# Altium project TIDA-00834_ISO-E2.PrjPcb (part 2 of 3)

## Sheet TIDA-00834_ISO-E2_Pg7_ COMPARATOR.SchDoc: COMPARATOR FOR ZCD
size 431 x 279 mm; Date: Not shown in title block; ApprovedBy: Not shown in title block; CheckedBy: Not shown in title block; Author: Not shown in title block; CompanyName: Not shown in title block; DrawnBy: Sreenivasa; Engineer: Not shown in title block; Organization: Not shown in title block; Address1: Not shown in title block; Address2: Not shown in title block; Address3: Not shown in title block; Address4: Not shown in title block; DocumentNumber: 1; Revision: Use project parameter SCH_Rev; SheetNumber: 7; SheetTotal: 12; PageSetup: Record=PageOptions¦CenterHorizontal=True¦CenterVertical=True¦PrintScale=1.00¦XCorrection=1.00¦YCorrection=1.00¦PrintKind=0¦BorderSize=5000000¦LeftOffset=0¦BottomOffset=0¦Orientation=2¦PaperLength=1000¦PaperWidth=1000¦Scale=100¦PaperSource=15¦PrintQuality=600¦MediaType=1¦DitherType=10¦PaperKind=Letter¦PrintScaleMode=1
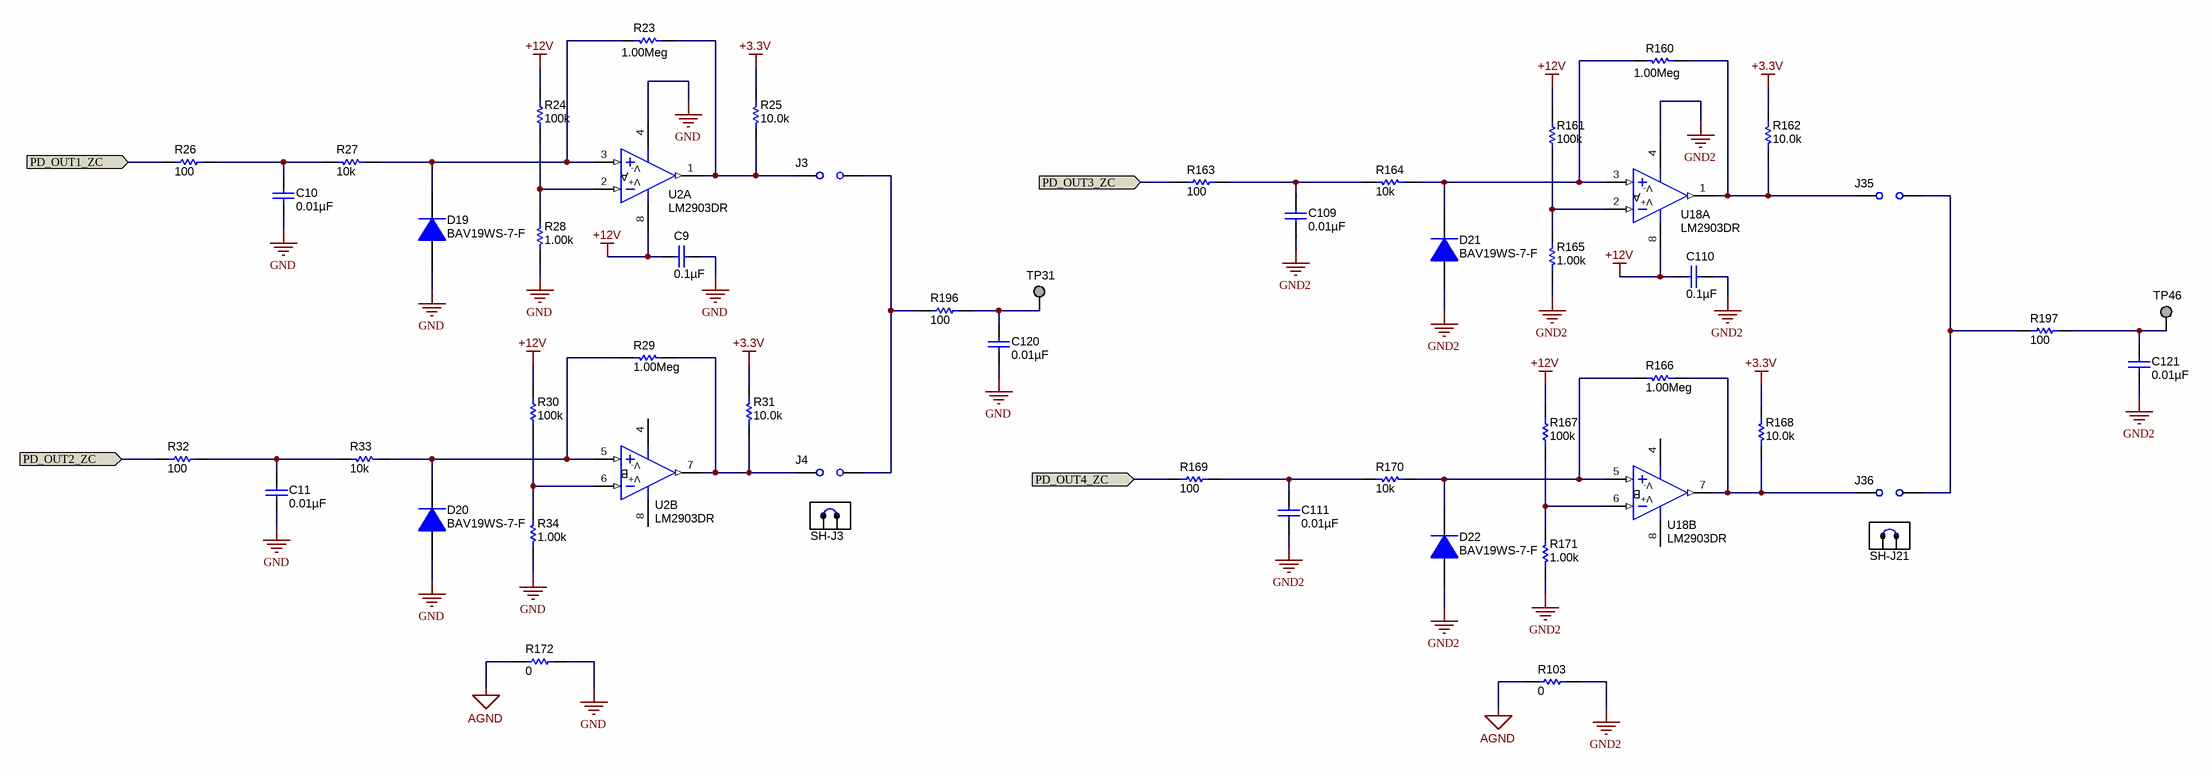
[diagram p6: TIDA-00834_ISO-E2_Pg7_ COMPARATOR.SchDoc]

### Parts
C9  ValueDisplayed: 0.1µF  [0603]  (hidden comment: 06033C104JAT2A)
C10  ValueDisplayed: 0.01µF  [0603]  (hidden comment: C1608C0G1E103J080AA)
C11  ValueDisplayed: 0.01µF  [0603]  (hidden comment: C1608C0G1E103J080AA)
C109  ValueDisplayed: 0.01µF  [0603]  (hidden comment: C1608C0G1E103J080AA)
C110  ValueDisplayed: 0.1µF  [0603]  (hidden comment: 06033C104JAT2A)
C111  ValueDisplayed: 0.01µF  [0603]  (hidden comment: C1608C0G1E103J080AA)
C120  ValueDisplayed: 0.01µF  [0603]  (hidden comment: C1608C0G1E103J080AA)
C121  ValueDisplayed: 0.01µF  [0603]  (hidden comment: C1608C0G1E103J080AA)
D19  BAV19WS-7-F  [SOD-323]
D20  BAV19WS-7-F  [SOD-323]
D21  BAV19WS-7-F  [SOD-323]
D22  BAV19WS-7-F  [SOD-323]
J3  JUMPER_2X100MIL  [HDR100_1X2]  (value not drawn)
J4  JUMPER_2X100MIL  [HDR100_1X2]  (value not drawn)
J35  JUMPER_2X100MIL  [HDR100_1X2]  (value not drawn)
J36  JUMPER_2X100MIL  [HDR100_1X2]  (value not drawn)
R23  value 1.00Meg  [0603]  (hidden comment: CRCW06031M00FKEA)
R24  ValueDisplayed: 100k  [0603]  (hidden comment: RC0603FR-07100KL)
R25  value 10.0k  [0603]  (hidden comment: CRCW060310K0FKEA)
R26  value 100  [0603]  (hidden comment: CRCW0603100RFKEA)
R27  value 10k  [0603]  (hidden comment: CRCW060310K0FKEA)
R28  value 1.00k  [1206]  (hidden comment: CRCW12061K00FKEA)
R29  value 1.00Meg  [0603]  (hidden comment: CRCW06031M00FKEA)
R30  ValueDisplayed: 100k  [0603]  (hidden comment: RC0603FR-07100KL)
R31  value 10.0k  [0603]  (hidden comment: CRCW060310K0FKEA)
R32  value 100  [0603]  (hidden comment: CRCW0603100RFKEA)
R33  value 10k  [0603]  (hidden comment: CRCW060310K0FKEA)
R34  value 1.00k  [1206]  (hidden comment: CRCW12061K00FKEA)
R103  value 0  [0805_HV]  (hidden comment: CRCW08050000Z0EA)
R160  value 1.00Meg  [0603]  (hidden comment: CRCW06031M00FKEA)
R161  ValueDisplayed: 100k  [0603]  (hidden comment: RC0603FR-07100KL)
R162  value 10.0k  [0603]  (hidden comment: CRCW060310K0FKEA)
R163  value 100  [0603]  (hidden comment: CRCW0603100RFKEA)
R164  value 10k  [0603]  (hidden comment: CRCW060310K0FKEA)
R165  value 1.00k  [1206]  (hidden comment: CRCW12061K00FKEA)
R166  value 1.00Meg  [0603]  (hidden comment: CRCW06031M00FKEA)
R167  ValueDisplayed: 100k  [0603]  (hidden comment: RC0603FR-07100KL)
R168  value 10.0k  [0603]  (hidden comment: CRCW060310K0FKEA)
R169  value 100  [0603]  (hidden comment: CRCW0603100RFKEA)
R170  value 10k  [0603]  (hidden comment: CRCW060310K0FKEA)
R171  value 1.00k  [1206]  (hidden comment: CRCW12061K00FKEA)
R172  value 0  [0805_HV]  (hidden comment: CRCW08050000Z0EA)
R196  value 100  [0603]  (hidden comment: CRCW0603100RFKEA)
R197  value 100  [0603]  (hidden comment: CRCW0603100RFKEA)
SH-J3  881545-2  [TE_881545-2]  (value not drawn)  (mechanical)
SH-J21  881545-2  [TE_881545-2]  (value not drawn)  (mechanical)
TP31  Suggest using a net name here  [Keystone1573-2]  (value not drawn)
TP46  Suggest using a net name here  [Keystone1573-2]  (value not drawn)
U2  LM2903DR  [D0008A_N]  (parts A,B of 2)
U18  LM2903DR  [D0008A_N]  (parts A,B of 2)

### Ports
PD_OUT1_ZC (in), PD_OUT2_ZC (in), PD_OUT3_ZC (in), PD_OUT4_ZC (in)

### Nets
+3.3V: R25.2 R31.2 R162.2 R168.2
+12V: C9.2 C110.2 R24.2 R30.2 R161.2 R167.2 U2.8(V+) U18.8(V+)
AGND: R103.1 R172.1
GND: C9.1 C10.1 C11.1 C120.1 D19.2(A) D20.2(A) R28.1 R34.1 R172.2 U2.4(V-)
GND2: C109.1 C110.1 C111.1 C121.1 D21.2(A) D22.2(A) R103.2 R165.1 R171.1 U18.4(V-)
PD_OUT1_ZC: R26.1 ; port PD_OUT1_ZC
PD_OUT2_ZC: R32.1 ; port PD_OUT2_ZC
PD_OUT3_ZC: R163.1 ; port PD_OUT3_ZC
PD_OUT4_ZC: R169.1 ; port PD_OUT4_ZC
NetC10_2: C10.2 R26.2 R27.1
NetC11_2: C11.2 R32.2 R33.1
NetC109_2: C109.2 R163.2 R164.1
NetC111_2: C111.2 R169.2 R170.1
NetC120_2: C120.2 R196.2 TP31.1
NetC121_2: C121.2 R197.2 TP46.1
NetD19_1: D19.1(K) R23.2 R27.2 U2.3(IN+)
NetD20_1: D20.1(K) R29.2 R33.2 U2.5(IN+)
NetD21_1: D21.1(K) R160.2 R164.2 U18.3(IN+)
NetD22_1: D22.1(K) R166.2 R170.2 U18.5(IN+)
NetJ3_1: J3.1 R23.1 R25.1 U2.1(OUT)
NetJ3_2: J3.2 J4.2 R196.1
NetJ4_1: J4.1 R29.1 R31.1 U2.7(OUT)
NetJ35_1: J35.1 R160.1 R162.1 U18.1(OUT)
NetJ35_2: J35.2 J36.2 R197.1
NetJ36_1: J36.1 R166.1 R168.1 U18.7(OUT)
NetR24_1: R24.1 R28.2 U2.2(IN-)
NetR30_1: R30.1 R34.2 U2.6(IN-)
NetR161_1: R161.1 R165.2 U18.2(IN-)
NetR167_1: R167.1 R171.2 U18.6(IN-)

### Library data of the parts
C9 C110 = 06033C104JAT2A: CAP, CERM, 0.1uF, 25V, +/-5%, X7R, 0603; Manufacturer: AVX; Polarized: N; CompType: Capacitor; U/M: EA; Cap_F: 0.0000001; Tolerance_%: 5; ESR_Ohm: 0.05; Value1: 0.05 ohm; VDC_V: 25; TaMin_C: -55; TaMax_C: 125
C10 C11 C109 C111 C120 C121 = C1608C0G1E103J: CAP, CERM, 0.01uF, 25V, +/-5%, C0G/NP0, 0603; Manufacturer: TDK; Polarized: N; CompType: Capacitor; U/M: EA; Cap_F: 0.00000001; Tolerance_%: 5; Value1: Unknown; VDC_V: 25; TaMin_C: -55; TaMax_C: 125
D19-D22 = BAV19WS-7-F: Diode, Switching, 100 V, 0.2 A, SOD-323; Manufacturer: Diodes Inc.; U/M: EA; Vf_V: 1.25; Value: 100V; Value1: 0.2A; Value2: 1.25V; Io_A: 0.2; Vr_V: 100; TJmax_C: 150; SizeAreaWB_mm2: 8.695; SizeArea_mm2: 3.645; SizeX_mm: 2.7; SizeY_mm: 1.35; SizeZ_mm: 1; AEC Category: Q101
J3 J4 J35 J36 = JUMPER_2X100MIL: Header, Male 2-pin, 100mil spacing,; Manufacturer: Sullins; PartNumber: PEC02SAAN; area: 20000; Value: PEC02SAAN
R23 R29 R160 R166 = CRCW06031M00FKEA: RES, 1.00Meg ohm, 1%, 0.1W, 0603; Manufacturer: Vishay-Dale; CompType: Resistor; Res_ohm: 1000000; Value_Code: 1M00; Tolerance_%: 1; Power_W: 0.1; VDC_V: 75; TempCo: 100 ppm/C; EIA_Code: E96; U/M: EA
R24 R30 R161 R167 = RC0603FR-07100KL: RES, 100 k, 1%, 0.1 W, 0603; Manufacturer: Yageo America; CompType: Resistor; Value: 100k; Res_ohm: 100000; Tolerance_%: 1; Power_W: 0.1; Value2: 0.1W; VDC_V: 150; TempCo: 200 ppm/C; EIA_Code: E96; U/M: EA; AEC Category: Q200
R25 R31 R162 R168 = CRCW060310K0FKEA: RES, 10.0k ohm, 1%, 0.1W, 0603; Manufacturer: Vishay-Dale; CompType: Resistor; Res_ohm: 10000; Value_Code: 10k0; Tolerance_%: 1; Power_W: 0.1; VDC_V: 75; TempCo: 100 ppm/C; EIA_Code: E96; U/M: EA
R26 R32 R163 R169 R196 R197 = CRCW0603100RFKEA: RES, 100 ohm, 1%, 0.1W, 0603; Manufacturer: Vishay-Dale; CompType: Resistor; Value_Code: 100R; Tolerance_%: 1; Power_W: 0.1; VDC_V: 75; TempCo: 100 ppm/C; EIA_Code: E96; U/M: EA
R27 R33 R164 R170 = RNCF0603TKY10K0: RES, 10.0k ohm, 1%, 0.1W, 0603; Manufacturer: Stackpole Electronics Inc; CompType: Resistor; Res_ohm: 10000; Value_Code: 10k0; Tolerance_%: 0.01; Value1: 0.01%; Power_W: 0.063; Value2: 0.063W; VDC_V: 50; TempCo: 5 ppm/C; U/M: EA
R28 R34 R165 R171 = CRCW12061K00FKEA: RES, 1.00k ohm, 1%, 0.25W, 1206; Manufacturer: Vishay-Dale; CompType: Resistor; Res_ohm: 1000; Value_Code: 1k00; Tolerance_%: 1; Power_W: 0.25; VDC_V: 200; TempCo: 100 ppm/C; EIA_Code: E96; U/M: EA
R103 R172 = CRCW0805330KJNEA: RES, 0 ohm, 5%, 0.125W, 0805; Manufacturer: Vishay-Dale; CompType: Resistor; Tolerance_%: 5; Power_W: 0.125; VDC_V: 150; TempCo: 200 ppm/C; EIA_Code: E24; U/M: EA
SH-J3 SH-J21 = 881545-2: Shunt, 100mil, Gold plated, Black; Manufacturer: TE Connectivity
TP31 TP46 = 1573-2: Terminal, Turret, TH, Double; Manufacturer: Keystone; CompType: Turret Terminal; U/M: EA
U2 U18 = LM2903D: Dual Comparator, D0008A; Manufacturer: Texas Instruments; CompType: OpAmp IC

## Sheet TIDA-00834_ISO-E2_Pg8_Split Rail Converter.SchDoc: SPLIT RAIL CONVERTER
size 431 x 279 mm; Date: Not shown in title block; ApprovedBy: Not shown in title block; CheckedBy: Not shown in title block; Author: Not shown in title block; CompanyName: Not shown in title block; DrawnBy: Sreenivasa; Engineer: Not shown in title block; Organization: Not shown in title block; Address1: Not shown in title block; Address2: Not shown in title block; Address3: Not shown in title block; Address4: Not shown in title block; DocumentNumber: 1; Revision: Use project parameter SCH_Rev; SheetNumber: 8; SheetTotal: 12; PageSetup: Record=PageOptions¦CenterHorizontal=True¦CenterVertical=True¦PrintScale=1.00¦XCorrection=1.00¦YCorrection=1.00¦PrintKind=0¦BorderSize=5000000¦LeftOffset=0¦BottomOffset=0¦Orientation=2¦PaperLength=1000¦PaperWidth=1000¦Scale=100¦PaperSource=15¦PrintQuality=600¦MediaType=1¦DitherType=10¦PaperKind=Letter¦PrintScaleMode=1
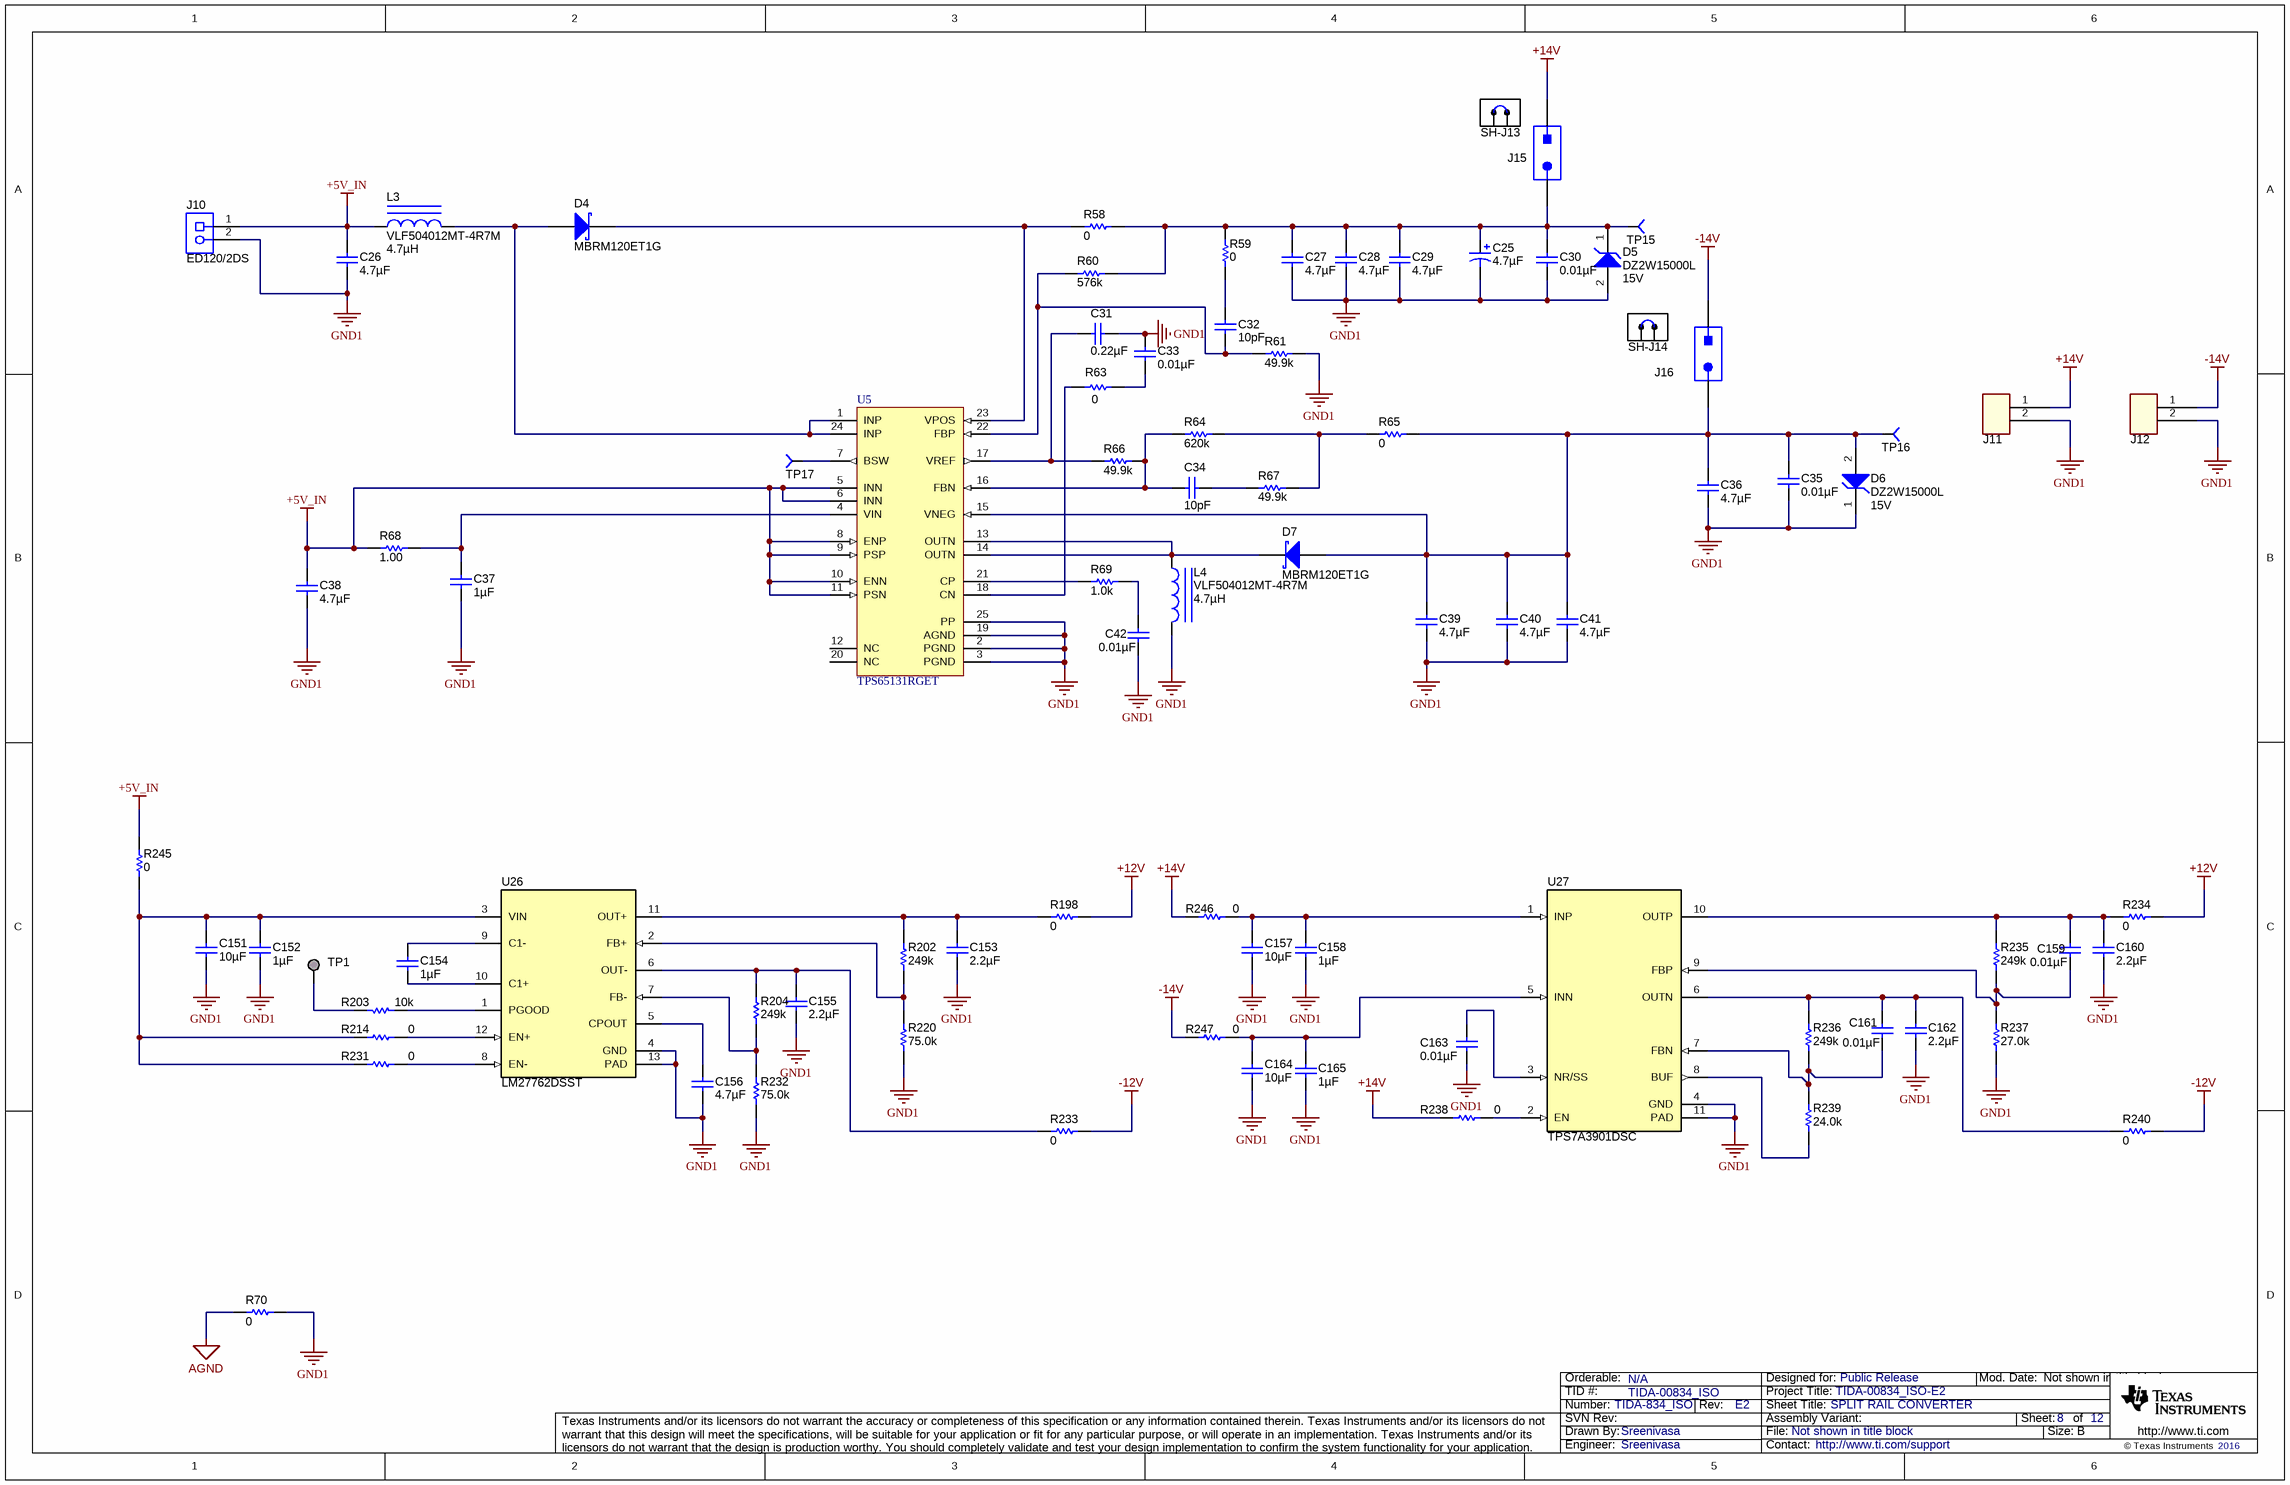
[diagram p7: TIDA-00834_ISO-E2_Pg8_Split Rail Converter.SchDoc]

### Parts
C25  ValueDisplayed: 4.7µF  [6032-28]  (hidden comment: 293D475X9025C2TE3)
C26  ValueDisplayed: 4.7µF  [1206]  (hidden comment: C3216X7R1E475M160AC)
C27  ValueDisplayed: 4.7µF  [1206]  (hidden comment: C3216X7R1E475M160AC)
C28  ValueDisplayed: 4.7µF  [1206]  (hidden comment: C3216X7R1E475M160AC)
C29  ValueDisplayed: 4.7µF  [1206]  (hidden comment: C3216X7R1E475M160AC)
C30  ValueDisplayed: 0.01µF  [0603]  (hidden comment: GRM188R70J103KA01D)
C31  ValueDisplayed: 0.22µF  [0603]  (hidden comment: C0603C224K9RACTU)
C32  ValueDisplayed: 10pF  [0603]  (hidden comment: C0603C100J5GACTU)
C33  ValueDisplayed: 0.01µF  [0603]  (hidden comment: GRM188R70J103KA01D)
C34  ValueDisplayed: 10pF  [0603]  (hidden comment: C0603C100J5GACTU)
C35  ValueDisplayed: 0.01µF  [0603]  (hidden comment: GRM188R70J103KA01D)
C36  ValueDisplayed: 4.7µF  [1206]  (hidden comment: C3216X7R1E475M160AC)
C37  ValueDisplayed: 1µF  [0603]  (hidden comment: GRM188R61E105KA12D)
C38  ValueDisplayed: 4.7µF  [1206]  (hidden comment: C3216X7R1E475M160AC)
C39  ValueDisplayed: 4.7µF  [1206]  (hidden comment: C3216X7R1E475M160AC)
C40  ValueDisplayed: 4.7µF  [1206]  (hidden comment: C3216X7R1E475M160AC)
C41  ValueDisplayed: 4.7µF  [1206]  (hidden comment: C3216X7R1E475M160AC)
C42  ValueDisplayed: 0.01µF  [0603]  (hidden comment: GRM188R70J103KA01D)
C151  ValueDisplayed: 10µF  [1210]
C152  ValueDisplayed: 1µF  [0603]  (hidden comment: GRM188R61E105KA12D)
C153  ValueDisplayed: 2.2µF  [0805_HV]  (hidden comment: C0805C225K8RACTU)
C154  ValueDisplayed: 1µF  [0603]  (hidden comment: GRM188R61E105KA12D)
C155  ValueDisplayed: 2.2µF  [0805_HV]  (hidden comment: C0805C225K8RACTU)
C156  ValueDisplayed: 4.7µF  [1206]  (hidden comment: C3216X7R1E475M160AC)
C157  ValueDisplayed: 10µF  [1210]
C158  ValueDisplayed: 1µF  [0603]  (hidden comment: GRM188R61E105KA12D)
C159  ValueDisplayed: 0.01µF  [0603]  (hidden comment: GRM188R70J103KA01D)
C160  ValueDisplayed: 2.2µF  [0805_HV]  (hidden comment: C0805C225K8RACTU)
C161  ValueDisplayed: 0.01µF  [0603]  (hidden comment: GRM188R70J103KA01D)
C162  ValueDisplayed: 2.2µF  [0805_HV]  (hidden comment: C0805C225K8RACTU)
C163  ValueDisplayed: 0.01µF  [0603]  (hidden comment: GRM188R70J103KA01D)
C164  ValueDisplayed: 10µF  [1210]
C165  ValueDisplayed: 1µF  [0603]  (hidden comment: GRM188R61E105KA12D)
D4  MBRM120ET1G  [POWERMITE]
D5  DZ2W15000L  value 15V  [SOD-123]
D6  DZ2W15000L  value 15V  [SOD-123]
D7  MBRM120ET1G  [POWERMITE]
J10  ED120/2DS  [CONN_ED120-2DS]
J11  CON-OSTVN02A150  [CN2_MTB_P100_PD80_D1.1_S5.54X6.5_STACK]  (value not drawn)
J12  CON-OSTVN02A150  [CN2_MTB_P100_PD80_D1.1_S5.54X6.5_STACK]  (value not drawn)
J15  5-146280-2  [TSW-102-07-G-S]  (value not drawn)
J16  5-146280-2  [TSW-102-07-G-S]  (value not drawn)
L3  VLF504012MT-4R7M  ValueDisplayed: 4.7µH  [IND_VLF504012]
L4  VLF504012MT-4R7M  ValueDisplayed: 4.7µH  [IND_VLF504012]
R58  value 0  [1206]  (hidden comment: CRCW12060000Z0EA)
R59  ValueDisplayed: 0  [0603]  (hidden comment: CRCW06030000Z0EA)
R60  ValueDisplayed: 576k  [0603]  (hidden comment: CRCW0603576KFKEA)
R61  ValueDisplayed: 49.9k  [0603]  (hidden comment: RG1608P-4992-B-T5)
R63  ValueDisplayed: 0  [0603]  (hidden comment: CRCW06030000Z0EA)
R64  ValueDisplayed: 620k  [0603]  (hidden comment: CRCW0603620KFKEA)
R65  ValueDisplayed: 0  [0603]  (hidden comment: CRCW06030000Z0EA)
R66  ValueDisplayed: 49.9k  [0603]  (hidden comment: RG1608P-4992-B-T5)
R67  ValueDisplayed: 49.9k  [0603]  (hidden comment: RG1608P-4992-B-T5)
R68  ValueDisplayed: 1.00  [0603]  (hidden comment: CR0603-J/-1R0ELF)
R69  ValueDisplayed: 1.0k  [0603]  (hidden comment: CRCW06031K00JNEA)
R70  value 0  [0805_HV]  (hidden comment: CRCW08050000Z0EA)
R198  ValueDisplayed: 0  [0603]  (hidden comment: CRCW06030000Z0EA)
R202  ValueDisplayed: 249k  [0603]  (hidden comment: CRCW0603249KFKEA)
R203  value 10k  [0603]  (hidden comment: CRCW060310K0FKEA)
R204  ValueDisplayed: 249k  [0603]  (hidden comment: CRCW0603249KFKEA)
R214  ValueDisplayed: 0  [0603]  (hidden comment: CRCW06030000Z0EA)
R220  ValueDisplayed: 75.0k  [0603]  (hidden comment: CRCW060375K0FKEA)
R231  ValueDisplayed: 0  [0603]  (hidden comment: CRCW06030000Z0EA)
R232  ValueDisplayed: 75.0k  [0603]  (hidden comment: CRCW060375K0FKEA)
R233  ValueDisplayed: 0  [0603]  (hidden comment: CRCW06030000Z0EA)
R234  ValueDisplayed: 0  [0603]  (hidden comment: CRCW06030000Z0EA)
R235  ValueDisplayed: 249k  [0603]  (hidden comment: CRCW0603249KFKEA)
R236  ValueDisplayed: 249k  [0603]  (hidden comment: CRCW0603249KFKEA)
R237  ValueDisplayed: 27.0k  [0603]  (hidden comment: RC0603FR-0727KL)
R238  ValueDisplayed: 0  [0603]  (hidden comment: CRCW06030000Z0EA)
R239  ValueDisplayed: 24.0k  [0603]  (hidden comment: RC0603FR-0724KL)
R240  ValueDisplayed: 0  [0603]  (hidden comment: CRCW06030000Z0EA)
R245  ValueDisplayed: 0  [1206]  (hidden comment: CRCW12060000Z0EA)
R246  ValueDisplayed: 0  [0603]  (hidden comment: CRCW06030000Z0EA)
R247  ValueDisplayed: 0  [0603]  (hidden comment: CRCW06030000Z0EA)
SH-J13  881545-2  [TE_881545-2]  (value not drawn)  (mechanical)
SH-J14  881545-2  [TE_881545-2]  (value not drawn)  (mechanical)
TP1  Pogo Pad  [PogoPad]  (value not drawn)  (no BOM)
TP15  TP-5001-BLACK  [TH-40]  (value not drawn)
TP16  TP-5001-BLACK  [TH-40]  (value not drawn)
TP17  TP-040_RND  [TP-040_RND]  (value not drawn)
U5  TPS65131RGET  [RGE0024B]
U26  LM27762DSST  [DSS0012B]
U27  TPS7A3901DSC  [DSC0010J]

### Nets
+5V_IN: C26.1 C38.1 J10.1 L3.1 R68.1 R245.2 U5.5(INN) U5.6(INN) U5.8(ENP) U5.9(PSP) U5.10(ENN) U5.11(PSN)
+12V: R198.2 R234.2
+14V: J11.1 J15.1 R238.1 R246.1
-12V: R233.2 R240.2
-14V: J12.1 J16.1 R247.1
AGND: R70.1
GND1: C25.2(-) C26.2 C27.2 C28.2 C29.2 C30.2 C31.1 C33.1 C35.2 C36.2 C37.2 C38.2 C39.2 C40.2 C41.2 C42.2 C151.1 C152.2 C153.2 C155.2 C156.2 C157.1 C158.2 C160.2 C162.2 C163.2 C164.1 C165.2 D5.2(A) D6.1(K) J10.2 J11.2 J12.2 L4.2 R61.2 R70.2 R220.1 R232.1 R237.1 U5.2(PGND) U5.3(PGND) U5.19(AGND) U5.25(PP) U26.4(GND) U26.13(PAD) U27.4(GND) U27.11(PAD)
NetC25_1: C25.1(+) C27.1 C28.1 C29.1 C30.1 D5.1(K) J15.2 R58.2 R59.2 R60.2 TP15.1
NetC31_2: C31.2 R66.1 U5.17(VREF)
NetC32_1: C32.1 R59.1
NetC32_2: C32.2 R60.1 R61.1 U5.22(FBP)
NetC33_2: C33.2 R63.2
NetC34_1: C34.1 R67.1
NetC34_2: C34.2 R64.1 R66.2 U5.16(FBN)
NetC35_1: C35.1 C36.1 C39.1 C40.1 C41.1 D6.2(A) D7.2(A) J16.2 R65.2 TP16.1 U5.15(VNEG)
NetC37_1: C37.1 R68.2 U5.4(VIN)
NetC42_1: C42.1 R69.2
NetC151_2: C151.2 C152.1 R214.1 R231.1 R245.1 U26.3(VIN)
NetC153_1: C153.1 R198.1 R202.2 U26.11(OUT+)
NetC154_1: C154.1 U26.9(C1-)
NetC154_2: C154.2 U26.10(C1+)
NetC155_1: C155.1 R204.2 R233.1 U26.6(OUT-)
NetC156_1: C156.1 U26.5(CPOUT)
NetC157_2: C157.2 C158.1 R246.2 U27.1(INP)
NetC159_1: C159.1 C160.1 R234.1 R235.2 U27.10(OUTP)
NetC159_2: C159.2 R235.1 R237.2 U27.9(FBP)
NetC161_1: C161.1 C162.1 R236.2 R240.1 U27.6(OUTN)
NetC161_2: C161.2 R236.1 R239.2 U27.7(FBN)
NetC163_1: C163.1 U27.3(NR/SS)
NetC164_2: C164.2 C165.1 R247.2 U27.5(INN)
NetD4_1: D4.1(K) R58.1 U5.23(VPOS)
NetD4_2: D4.2(A) L3.2 U5.1(INP) U5.24(INP)
NetD7_1: D7.1(K) L4.1 U5.13(OUTN) U5.14(OUTN)
NetR63_1: R63.1 U5.18(CN)
NetR64_2: R64.2 R65.1 R67.2
NetR69_1: R69.1 U5.21(CP)
NetR202_1: R202.1 R220.2 U26.2(FB+)
NetR203_1: R203.1 TP1.1
NetR203_2: R203.2 U26.1(PGOOD)
NetR204_1: R204.1 R232.2 U26.7(FB-)
NetR214_2: R214.2 U26.12(EN+)
NetR231_2: R231.2 U26.8(EN-)
NetR238_2: R238.2 U27.2(EN)
NetR239_1: R239.1 U27.8(BUF)
NetTP17_1: TP17.1 U5.7(BSW)

Not connected (* = marked no-connect by the designer): U5 12(NC) 20(NC)

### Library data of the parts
C25 = 293D475X9025C2TE3: CAP, TA, 4.7 µF, 25 V, +/- 10%, 2 ohm, SMD; Manufacturer: Vishay-Sprague; Polarized: Y; CompType: Capacitor; Value: 4.7uF; U/M: EA; Cap_F: 0.0000047; Tolerance_%: 10; Value1: 2 ohm; VDC_V: 25; Value2: 25V; ESR_ohm: 2; IRMS_A: 0.24; TaMin_C: -55; TaMax_C: 125; Cap_Case: C
C26-C29 C36 C38-C41 C156 = C3216X7R1E475M: CAP, CERM, 4.7 µF, 25 V, +/- 20%, X7R, 1206; Manufacturer: TDK; Polarized: N; CompType: Capacitor; Value: 4.7uF; U/M: EA; Cap_F: 0.0000047; Tolerance_%: 20; ESR_ohm: 0.0063; Value1: 0.0063 ohm; VDC_V: 25; Value2: 25V; TaMin_C: -55; TaMax_C: 125
C30 C33 C35 C42 C159 C161 C163 = GRM188R70J103KA01D: CAP, CERM, 0.01 µF, 6.3 V, +/- 10%, X7R, 0603; Manufacturer: MuRata; Polarized: N; CompType: Capacitor; Value: 0.01uF; U/M: EA; Cap_F: 0.00000001; Tolerance_%: 10; Value1: Unknown; VDC_V: 6.3; Value2: 6.3V; TaMin_C: -55; TaMax_C: 125
C31 = C0603C224K4RACTU: CAP, CERM, 0.22 µF, 6.3 V, +/- 10%, X7R, 0603; Manufacturer: Kemet; Polarized: N; CompType: Capacitor; Value: 0.22uF; U/M: EA; Cap_F: 0.00000022; Tolerance_%: 10; Value1: Unknown; VDC_V: 16; Value2: 16V; TaMin_C: -55; TaMax_C: 125
C32 C34 = C0603C100J5GACTU: CAP, CERM, 10 pF, 50 V, +/- 5%, C0G/NP0, 0603; Manufacturer: Kemet; Polarized: N; CompType: Capacitor; Value: 10pF; U/M: EA; Cap_F: 0.00000000001; Tolerance_%: 5; Value1: Unknown; VDC_V: 50; Value2: 50V; TaMin_C: -55; TaMax_C: 125
C37 C152 C154 C158 C165 = GRM188R61E105KA12D: CAP, CERM, 1 µF, 25 V, +/- 10%, X5R, 0603; Manufacturer: MuRata; Polarized: N; CompType: Capacitor; Value: 1uF; U/M: EA; Cap_F: 0.000001; Tolerance_%: 10; Value1: Unknown; VDC_V: 25; Value2: 25V; TaMin_C: -55; TaMax_C: 85
C151 C157 C164 = GMK325AB7106MM-T: CAP, CERM, 10uF, 35V, +/-20%, X7R, 1210; Manufacturer: Taiyo Yuden; Polarized: N; CompType: Capacitor; U/M: EA; Cap_F: 0.00001; Tolerance_%: 20; Value1: Unknown; VDC_V: 35; TaMin_C: -55; TaMax_C: 125
C153 C155 C160 C162 = C0805C225K8RACTU: CAP, CERM, 2.2uF, 10V, +/-10%, X7R, 0805; Manufacturer: Kemet; Polarized: N; CompType: Capacitor; U/M: EA; Cap_F: 0.0000022; Tolerance_%: 10; ESR_Ohm: 0.008; Value1: 0.008 ohm; IRMS_A: 15.55; TaMin_C: -55; TaMax_C: 125; Cap_Case: 0805
D4 D7 = MBRM120ET1G: Diode, Schottky, 20 V, 1 A, POWERMITE; Manufacturer: ON Semiconductor; U/M: EA; Vf_V: 0.53; Value: 20V; Value1: 1A; Value2: 0.53V; Io_A: 1; Vr_V: 20
D5 D6 = DZ2W15000L: Diode, Zener, 15V, 1W, SOD-123; Manufacturer: Panasonic
J10 = ED120/2DS: TERMINAL BLOCK 5.08MM VERT 2POS, TH; Manufacturer: On-Shore Technology; SymbolCreator: a0412235; U/M: EA
J11 J12 = CON-OSTVN02A150: Terminal Block, 4x1, 2.54mm, TH; Manufacturer: On Shore Technology Inc; SymbolCreator: x0120606
J15 J16 = TSW-102-07-G-S: Header, 100mil, 2x1, Gold, TH; Manufacturer: TE Connectivity; SymbolCreator: a0412235; U/M: EA
L3 L4 = VLF504012MT-4R7M: Inductor, Shielded, Ferrite, 4.7uH, 1.83A, 0.1 ohm, SMD; Manufacturer: TDK; Ind_H: 4.7E-6; Imax_A: 1.83; Irms: 1.83A @ 40C rise; Isat: 1.94A @ 30% inductance drop; DCR_ohm: 0.1; Value1: 0.1 ohm; U/M: EA
R58 = CRCW12060000Z0EA: RES, 0 ohm, 5%, 0.25W, 1206; Manufacturer: Vishay-Dale; CompType: Resistor; Value_Code: 0000; Tolerance_%: 5; Power_W: 0.25; VDC_V: 200; TempCo: 200 ppm/C; EIA_Code: E24; U/M: EA
R59 R63 R65 R198 R214 R231 R233 R234 R238 R240 R246 R247 = CRCW06030000Z0EA: RES, 0, 5%, 0.1 W, 0603; Manufacturer: Vishay-Dale; CompType: Resistor; Value: 0; Value_Code: 0000; Tolerance_%: 5; Power_W: 0.1; Value2: 0.1W; VDC_V: 75; TempCo: 200 ppm/C; EIA_Code: E24; U/M: EA
R60 = CRCW0603576KFKEA: RES, 576 k, 1%, 0.1 W, 0603; Manufacturer: Vishay-Dale; CompType: Resistor; Value: 576k; Res_ohm: 576000; Tolerance_%: 1; Power_W: 0.1; Value2: 0.1W; VDC_V: 75; TempCo: 100 ppm/C; EIA_Code: E96; U/M: EA
R61 R66 R67 = RG1608P-4992-B-T5: RES, 49.9 k, 0.1%, 0.1 W, 0603; Manufacturer: Susumu Co Ltd; CompType: Resistor; Value: 49.9k; Res_ohm: 49900; Value_Code: 49k9; Tolerance_%: 0.1; Value2: 0.1W; VDC_V: 75; TempCo: 25 ppm/C; EIA_Code: E192; U/M: EA
R64 = RC0603FR-07620KL: RES SMD 620K OHM 1% 1/10W 0603; Manufacturer: Vishay-Dale; CompType: Resistor; Res_ohm: 620000; Tolerance_%: 1; Power_W: 0.1; Value2: 0.1W; VDC_V: 150; TempCo: 200 ppm/C; U/M: EA
R68 = RT0603DRE071RL: RES SMD 1 OHM 5% 1/10W 0603; Manufacturer: Bourns inc; CompType: Resistor; Value: 1.00; Res_ohm: 1; Value_Code: 1R00; Tolerance_%: 0.5; Value1: 0.5%; Power_W: 0.1; Value2: 0.1W; VDC_V: 75; TempCo: 50 ppm/C; EIA_Code: E192; U/M: EA
R69 = CRCW06031K00JNEA: RES, 1.0 k, 5%, 0.1 W, 0603; Manufacturer: Vishay-Dale; CompType: Resistor; Value: 1.0k; Res_ohm: 1000; Value_Code: 1k00; Tolerance_%: 5; Power_W: 0.1; Value2: 0.1W; VDC_V: 75; TempCo: 200 ppm/C; EIA_Code: E24; U/M: EA
R70 = CRCW0805330KJNEA: as R103 on sheet TIDA-00834_ISO-E2_Pg7_ COMPARATOR
R202 R204 R235 R236 = CRCW0603249KFKEA: RES, 249 k, 1%, 0.1 W, 0603; Manufacturer: Vishay-Dale; CompType: Resistor; Value: 249k; Res_ohm: 249000; Tolerance_%: 1; Power_W: 0.1; Value2: 0.1W; VDC_V: 75; TempCo: 100 ppm/C; SizeArea_mm2: 1.28; SizeX_mm: 1.6; SizeY_mm: 0.8; EIA_Code: E96; U/M: EA; AEC Category: Q200
R203 = RNCF0603TKY10K0: as R27 on sheet TIDA-00834_ISO-E2_Pg7_ COMPARATOR
R220 R232 = CRCW060375K0FKEA: RES, 75.0 k, 1%, 0.1 W, 0603; Manufacturer: Vishay-Dale; CompType: Resistor; Value: 75.0k; Res_ohm: 75000; Value_Code: 75k0; Tolerance_%: 1; Power_W: 0.1; Value2: 0.1W; VDC_V: 75; TempCo: 100 ppm/C; SizeArea_mm2: 1.28; SizeX_mm: 1.6; SizeY_mm: 0.8; EIA_Code: E96; U/M: EA; AEC Category: Q200
R237 = RC0603FR-0727KL: RES, 27.0 k, 1%, 0.1 W, 0603; Manufacturer: Yageo America; CompType: Resistor; Value: 27.0k; Res_ohm: 27000; Value_Code: 27k0; Tolerance_%: 1; Power_W: 0.1; Value2: 0.1W; VDC_V: 150; TempCo: 200 ppm/C; SizeArea_mm2: 1.28; SizeX_mm: 1.6; SizeY_mm: 0.8; U/M: EA; AEC Category: Q200; Green_Lifecycle: Active; Green_REACh: Passed
R239 = RC0603FR-0724KL: RES, 24.0 k, 1%, 0.1 W, 0603; Manufacturer: Yageo America; CompType: Resistor; Value: 24.0k; Res_ohm: 24000; Value_Code: 24k0; Tolerance_%: 1; Power_W: 0.1; Value2: 0.1W; VDC_V: 150; TempCo: 200 ppm/C; SizeArea_mm2: 1.28; SizeX_mm: 1.6; SizeY_mm: 0.8; U/M: EA; AEC Category: Q200; Green_Lifecycle: Active; Green_REACh: Passed
R245 = CRCW12060000Z0EA: RES, 0, 5%, 0.25 W, 1206; Manufacturer: Vishay-Dale; CompType: Resistor; Value: 0; Value_Code: 0000; Tolerance_%: 5; Power_W: 0.25; Value2: 0.25W; VDC_V: 200; TempCo: 200 ppm/C; SizeArea_mm2: 5.12; SizeX_mm: 3.2; SizeY_mm: 1.6; SizeZ_mm: 1.35; EIA_Code: E24; U/M: EA; AEC Category: Q200
SH-J13 SH-J14 = 881545-2: as SH-J3 on sheet TIDA-00834_ISO-E2_Pg7_ COMPARATOR
TP1 = PogoPad: Pad for Pogo Pin Connector; SymbolCreator: codlsc
TP15 TP16 = TP-5001-BLACK: Test Point,  Black, Thru Hole Color Keyed; Manufacturer: Keystone; PartNumber: 5001; area: 10.000; Value: 5001
TP17 = TP-040_RND: Test Point, O.040 Hole; Manufacturer: STD; Value: STD
U5 = TPS65131RGET: Postive and Negative Output DC-DC Converter, 2.7 to 5.5 V, -40 to 85 degC, 24-pin QFN (RGE24), Green (RoHS & no Sb/Br); Manufacturer: Texas Instruments; Alternate Manufacturer: None; Alternate PartNumber: Equivalent; Iq(Typ)(mA): 0.5; Rating: Catalog; SubFamily: LCD/OLED Display Bias Solutions; Switching Frequency(Typ)(kHz): 1400; Synchronous Rectification: TRUE; Topology: Boost, Inverting Buck/Boost; Vin(Max)(V): 5.5; Vin(Min)(V): 2.7
U26 = LM27762DSSR: Low-Noise Regulated Switched-Capacitor Voltage Inverter and Positive LDO, DSS0012B; Manufacturer: Texas Instruments; SymbolCreator: Altium; SizeArea_mm2: 6; SizeAreaWB_mm2: 12; SizeX_mm: 2; SizeY_mm: 3; SizeZ_mm: 0.8; CompType: IC; U/M: EA
U27 = TPS7A3901DSC: Wide-VIN (±33 V), 150-mA, Spilt-Rail Output, Positive and Negative LDO Voltage Regulator with Startup Tracking, DSC0010J; Manufacturer: Texas Instruments; SymbolCreator: Altium; SizeArea_mm2: 9; SizeAreaWB_mm2: 16; SizeX_mm: 3; SizeZ_mm: 0.8; CompType: IC; U/M: EA

## Sheet TIDA-00834_ISO-E2_Pg9_LDO.SchDoc: LDO
size 431 x 279 mm; Date: Not shown in title block; ApprovedBy: Not shown in title block; CheckedBy: Not shown in title block; Author: Not shown in title block; CompanyName: Not shown in title block; DrawnBy: Sreenivasa; Engineer: Not shown in title block; Organization: Not shown in title block; Address1: Not shown in title block; Address2: Not shown in title block; Address3: Not shown in title block; Address4: Not shown in title block; DocumentNumber: 1; Revision: Use project parameter SCH_Rev; SheetNumber: 9; SheetTotal: 12; PageSetup: Record=PageOptions¦CenterHorizontal=True¦CenterVertical=True¦PrintScale=1.00¦XCorrection=1.00¦YCorrection=1.00¦PrintKind=0¦BorderSize=5000000¦LeftOffset=0¦BottomOffset=0¦Orientation=2¦PaperLength=1000¦PaperWidth=1000¦Scale=100¦PaperSource=15¦PrintQuality=600¦MediaType=1¦DitherType=10¦PaperKind=Letter¦PrintScaleMode=1
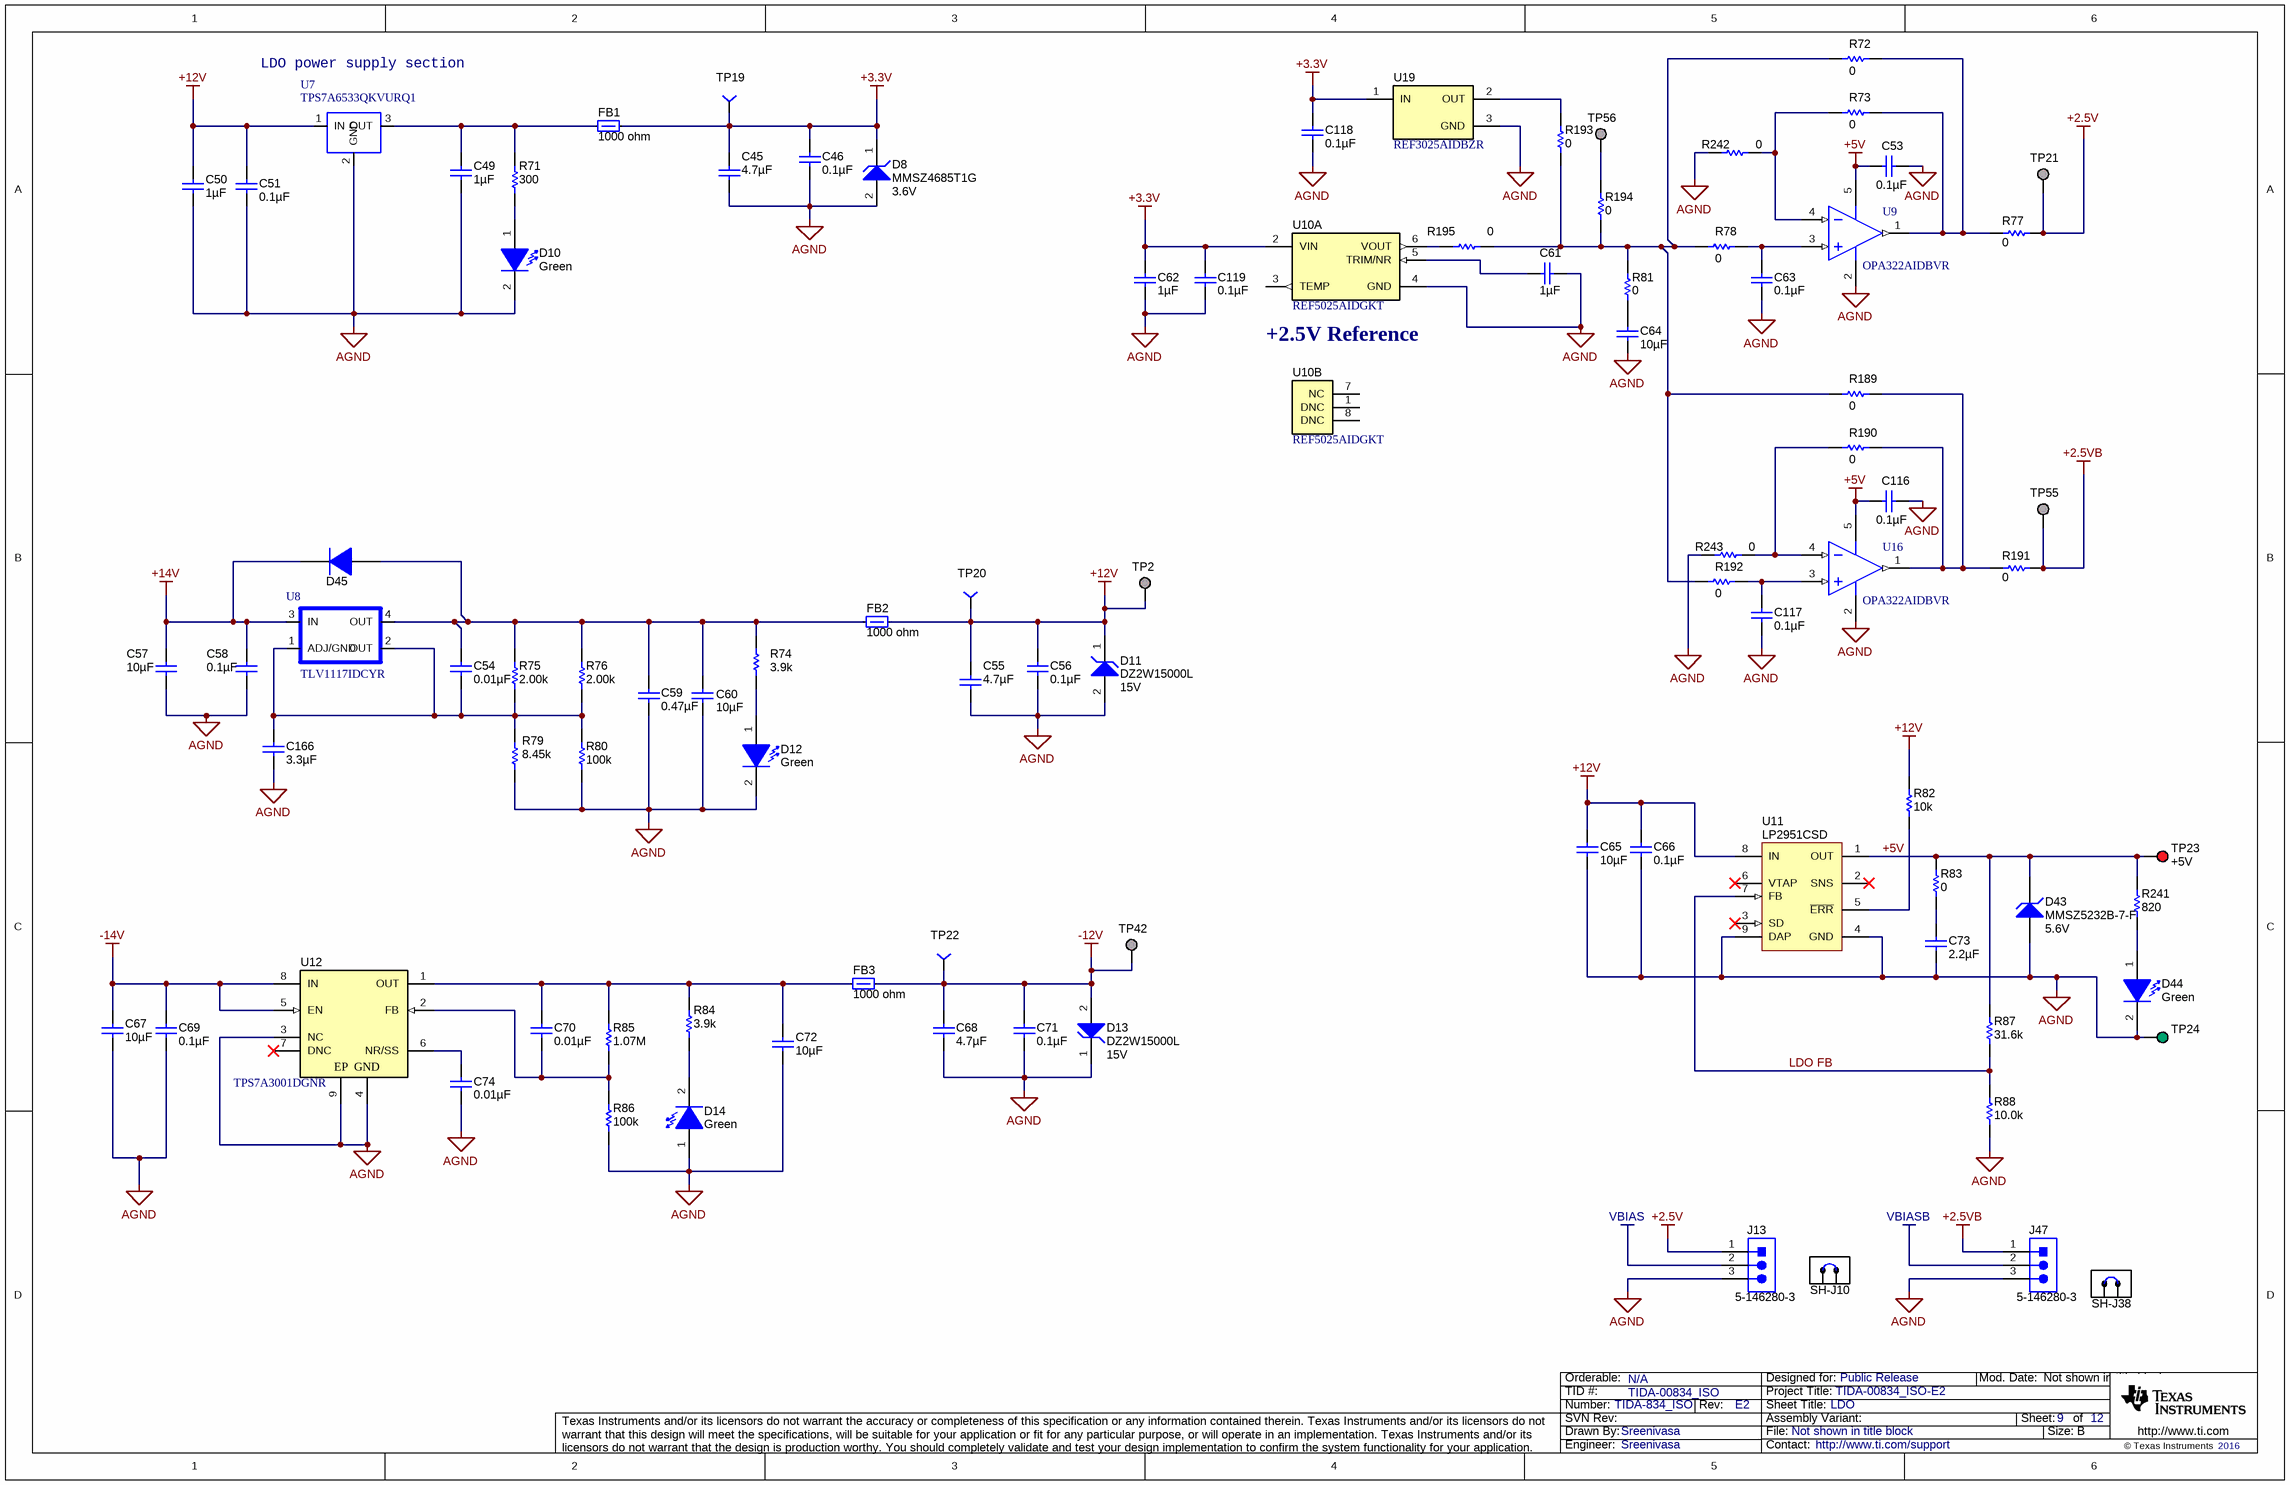
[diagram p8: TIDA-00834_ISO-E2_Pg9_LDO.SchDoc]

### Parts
C45  ValueDisplayed: 4.7µF  [0805_HV]  (hidden comment: C2012X5R1H475M125AB)
C46  ValueDisplayed: 0.1µF  [0603]  (hidden comment: C0603C104K5RACTU)
C49  ValueDisplayed: 1µF  [0603]  (hidden comment: CGA3E3X5R1H105K080AB)
C50  ValueDisplayed: 1µF  [0603]  (hidden comment: CGA3E3X5R1H105K080AB)
C51  ValueDisplayed: 0.1µF  [0603]  (hidden comment: C0603C104K5RACTU)
C53  ValueDisplayed: 0.1µF  [0603]  (hidden comment: C0603C104J4RACTU)
C54  ValueDisplayed: 0.01µF  [0603]  (hidden comment: 06031C103KAT2A)
C55  ValueDisplayed: 4.7µF  [0805_HV]  (hidden comment: C2012X5R1H475M125AB)
C56  ValueDisplayed: 0.1µF  [0603]  (hidden comment: C0603C104K5RACTU)
C57  ValueDisplayed: 10µF  [1210]  (hidden comment: GMK325AB7106MM-T)
C58  ValueDisplayed: 0.1µF  [0603]  (hidden comment: C0603C104K5RACTU)
C59  ValueDisplayed: 0.47µF  [0603]  (hidden comment: UMK107ABJ474KA-T)
C60  ValueDisplayed: 10µF  [1210]  (hidden comment: GMK325AB7106MM-T)
C61  ValueDisplayed: 1µF  [0805_HV]  (hidden comment: C0805C105K8RACTU)
C62  ValueDisplayed: 1µF  [0805_HV]  (hidden comment: C0805C105K8RACTU)
C63  ValueDisplayed: 0.1µF  [0603]  (hidden comment: C0603C104K8RACTU)
C64  ValueDisplayed: 10µF  [0603]  (hidden comment: EMK107BBJ106MA-T)
C65  ValueDisplayed: 10µF  [1206]  (hidden comment: 885012208069)
C66  ValueDisplayed: 0.1µF  [0603]  (hidden comment: 06033C104JAT2A)
C67  ValueDisplayed: 10µF  [1210]  (hidden comment: GMK325AB7106MM-T)
C68  ValueDisplayed: 4.7µF  [0805_HV]  (hidden comment: C2012X5R1H475M125AB)
C69  ValueDisplayed: 0.1µF  [0603]  (hidden comment: C0603C104K5RACTU)
C70  ValueDisplayed: 0.01µF  [0603]  (hidden comment: 06031C103KAT2A)
C71  ValueDisplayed: 0.1µF  [0603]  (hidden comment: C0603C104K5RACTU)
C72  ValueDisplayed: 10µF  [1210]  (hidden comment: GMK325AB7106MM-T)
C73  ValueDisplayed: 2.2µF  [0805_HV]  (hidden comment: C0805C225K8RACTU)
C74  ValueDisplayed: 0.01µF  [0603]  (hidden comment: 06031C103KAT2A)
C116  ValueDisplayed: 0.1µF  [0603]  (hidden comment: C0603C104J4RACTU)
C117  ValueDisplayed: 0.1µF  [0603]  (hidden comment: C0603C104K8RACTU)
C118  ValueDisplayed: 0.1µF  [0603]  (hidden comment: C0603C104K5RACTU)
C119  ValueDisplayed: 0.1µF  [0603]  (hidden comment: C0603C104K5RACTU)
C166  ValueDisplayed: 3.3µF  [0603]  (hidden comment: C1608X5R1V335K080AC)
D8  MMSZ4685T1G  value 3.6V  [SOD-123]
D10  value Green  [LG L29K_GREEN]  (hidden comment: LG L29K-G2J1-24-Z)
D11  DZ2W15000L  value 15V  [SOD-123]
D12  value Green  [LG L29K_GREEN]  (hidden comment: LG L29K-G2J1-24-Z)
D13  DZ2W15000L  value 15V  [SOD-123]
D14  value Green  [LG L29K_GREEN]  (hidden comment: LG L29K-G2J1-24-Z)
D43  MMSZ5232B-7-F  value 5.6V  [SOD-123]
D44  value Green  [LG L29K_GREEN]  (hidden comment: LG L29K-G2J1-24-Z)
D45  BAS316,115  [sod-323]  (value not drawn)
FB1  value 1000 ohm  [MMZ1608_095]  (hidden comment: MMZ1608B102CTA00)
FB2  value 1000 ohm  [MMZ1608_095]  (hidden comment: MMZ1608B102CTA00)
FB3  value 1000 ohm  [MMZ1608_095]  (hidden comment: MMZ1608B102CTA00)
J13  5-146280-3  [TE_5-146280-3]
J47  5-146280-3  [TE_5-146280-3]
R71  value 300  [0603]  (hidden comment: CRCW0603300RJNEA)
R72  value 0  [0603]  (hidden comment: CRCW06030000Z0EA)
R73  value 0  [0603]  (hidden comment: CRCW06030000Z0EA)
R74  value 3.9k  [0603]  (hidden comment: CRCW06033K90JNEA)
R75  ValueDisplayed: 2.00k  [1206]  (hidden comment: CRCW12062K00FKEA)
R76  ValueDisplayed: 2.00k  [1206]  (hidden comment: CRCW12062K00FKEA)
R77  value 0  [0603]  (hidden comment: CRCW06030000Z0EA)
R78  value 0  [0603]  (hidden comment: CRCW06030000Z0EA)
R79  ValueDisplayed: 8.45k  [0603]  (hidden comment: CRCW06038K45FKEA)
R80  ValueDisplayed: 100k  [0603]  (hidden comment: CRCW0603100KFKEA)
R81  value 0  [0603]  (hidden comment: CRCW06030000Z0EA)
R82  value 10k  [0603]  (hidden comment: CRCW060310K0FKEA)
R83  value 0  [0603]  (hidden comment: CRCW06030000Z0EA)
R84  value 3.9k  [0603]  (hidden comment: CRCW06033K90JNEA)
R85  ValueDisplayed: 1.07M  [0603]  (hidden comment: CRCW06031M07FKEA)
R86  ValueDisplayed: 100k  [0603]  (hidden comment: RC0603FR-07100KL)
R87  value 31.6k  [0603]  (hidden comment: CRCW060331K6FKEA)
R88  value 10.0k  [0603]  (hidden comment: CRCW060310K0FKEA)
R189  value 0  [0603]  (hidden comment: CRCW06030000Z0EA)
R190  value 0  [0603]  (hidden comment: CRCW06030000Z0EA)
R191  value 0  [0603]  (hidden comment: CRCW06030000Z0EA)
R192  value 0  [0603]  (hidden comment: CRCW06030000Z0EA)
R193  value 0  [0603]  (hidden comment: CRCW06030000Z0EA)
R194  value 0  [0603]  (hidden comment: CRCW06030000Z0EA)
R195  value 0  [0603]  (hidden comment: CRCW06030000Z0EA)
R241  ValueDisplayed: 820  [0603]  (hidden comment: RC0603FR-07820RL)
R242  value 0  [0603]  (hidden comment: CRCW06030000Z0EA)
R243  value 0  [0603]  (hidden comment: CRCW06030000Z0EA)
SH-J10  881545-2  [TE_881545-2]  (value not drawn)  (mechanical)
SH-J38  881545-2  [TE_881545-2]  (value not drawn)  (mechanical)
TP2  Suggest using a net name here  [Keystone1573-2]  (value not drawn)
TP19  TP1_PD40_D0.5_S50  [TP1_PD40_D0.5_S50]  (value not drawn)
TP20  TP1_PD40_D0.5_S50  [TP1_PD40_D0.5_S50]  (value not drawn)
TP21  Suggest using a net name here  [Keystone1573-2]  (value not drawn)
TP22  TP1_PD40_D0.5_S50  [TP1_PD40_D0.5_S50]  (value not drawn)
TP23  +5V  [Keystone5010]
TP24  (no value)  [Keystone5126]
TP42  Suggest using a net name here  [Keystone1573-2]  (value not drawn)
TP55  Suggest using a net name here  [Keystone1573-2]  (value not drawn)
TP56  Suggest using a net name here  [Keystone1573-2]  (value not drawn)
U7  TPS7A6533QKVURQ1  [KVU_1]
U8  TLV1117IDCYR  [DCY]
U9  OPA322AIDBVR  [DBV0005A_N]
U10  REF5025AIDGKT  [DGK0008A_N]  (parts A,B of 2)
U11  LP2951CSD  [SDC08A]
U12  TPS7A3001DGNR  [DGN0008D_N]
U16  OPA322AIDBVR  [DBV0005A_N]
U19  REF3025AIDBZR  [DBZ0003A_N]

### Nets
+2.5V: J13.1 R77.1 TP21.1
+2.5VB: J47.1 R191.1 TP55.1
+3.3V: C45.1 C46.1 C62.1 C118.1 C119.1 D8.1(K) FB1.2 TP19.1 U10.2(VIN) U19.1(IN)
+5V: C53.2 C116.2 D43.1(K) R83.2 R87.2 R241.2 TP23.1 U9.5(V+) U11.1(OUT) U16.5(V+)
+12V: C50.1 C51.1 C55.1 C56.1 C65.1 C66.1 D11.1(K) FB2.2 R82.2 TP2.1 TP20.1 U7.1(IN) U11.8(IN)
+14V: C57.1 C58.1 D45.1(K) U8.3(IN)
-12V: C68.2 C71.1 D13.2(A) FB3.2 TP22.1 TP42.1
-14V: C67.2 C69.1 U12.5(EN) U12.8(IN)
AGND: C45.2 C46.2 C49.2 C50.2 C51.2 C53.1 C55.2 C56.2 C57.2 C58.2 C59.2 C60.2 C61.2 C62.2 C63.1 C64.2 C65.2 C66.2 C67.1 C68.1 C69.2 C71.2 C72.1 C73.2 C74.1 C116.1 C117.1 C118.2 C119.2 C166.2 D8.2(A) D10.2(K) D11.2(A) D12.2(K) D13.1(K) D14.1(A) D43.2(A) D44.2(K) J13.3 J47.3 R79.1 R80.1 R86.1 R88.1 R242.2 R243.2 TP24.1 U7.2(GND) U9.2(V-) U10.4(GND) U11.4(GND) U11.9(DAP) U12.3(NC) U12.4(GND) U12.9(EP) U16.2(V-) U19.3(GND)
VBIAS: J13.2
VBIASB: J47.2
LDO FB: R87.1 R88.2 U11.7(FB)
NetC49_1: C49.1 FB1.1 R71.2 U7.3(OUT)
NetC54_1: C54.1 C59.1 C60.1 D45.2(A) FB2.1 R74.2 R75.2 R76.2 U8.4(OUT)
NetC54_2: C54.2 C166.1 R75.1 R76.1 R79.2 R80.2 U8.1(ADJ/GND) U8.2(OUT)
NetC61_1: C61.1 U10.5(TRIM/NR)
NetC63_2: C63.2 R78.1 U9.3(IN+)
NetC64_1: C64.1 R81.2
NetC70_1: C70.1 R85.1 R86.2 U12.2(FB)
NetC70_2: C70.2 C72.2 FB3.1 R84.2 R85.2 U12.1(OUT)
NetC73_1: C73.1 R83.1
NetC74_2: C74.2 U12.6(NR/SS)
NetC117_2: C117.2 R192.1 U16.3(IN+)
NetD10_1: D10.1(A) R71.1
NetD12_1: D12.1(A) R74.1
NetD14_2: D14.2(K) R84.1
NetD44_1: D44.1(A) R241.1
NetR72_1: R72.1 R73.1 R77.2 U9.1(OUT)
NetR72_2: R72.2 R78.2 R81.1 R189.2 R192.2 R193.2 R194.2 R195.2
NetR73_2: R73.2 R242.1 U9.4(IN-)
NetR82_1: R82.1 U11.5(~{ERR})
NetR189_1: R189.1 R190.1 R191.2 U16.1(OUT)
NetR190_2: R190.2 R243.1 U16.4(IN-)
NetR193_1: R193.1 U19.2(OUT)
NetR194_1: R194.1 TP56.1
NetR195_1: R195.1 U10.6(VOUT)

Not connected (* = marked no-connect by the designer): U10 1(DNC) 3(TEMP) 7(NC) 8(DNC); U11 2(SNS)* 3(SD)* 6(VTAP)*; U12 7(DNC)*

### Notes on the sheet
- LDO power supply section
- (near U10) +2.5V Reference

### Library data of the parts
C45 C55 C68 = C2012X5R1H475K125AB: CAP, CERM, 4.7uF, 50V, +/-10%, X5R, 0805; Manufacturer: TDK; Polarized: N; CompType: Capacitor; U/M: EA; Cap_F: 0.0000047; Tolerance_%: 10; Value1: Unknown; VDC_V: 50; TaMin_C: -55; TaMax_C: 85; Cap_Case: 0805
C46 C51 C56 C58 C69 C71 C118 C119 = C0603C104K5RACTU: CAP, CERM, 0.1uF, 50V, +/-10%, X7R, 0603; Manufacturer: Kemet; Polarized: N; CompType: Capacitor; U/M: EA; Cap_F: 0.0000001; Tolerance_%: 10; Value1: Unknown; VDC_V: 50; TaMin_C: -55; TaMax_C: 125
C49 C50 = GRM188R61H105KAALD: CAP, CERM, 1uF, 50V, +/-10%, X5R, 0603; Manufacturer: TDK; Polarized: N; CompType: Capacitor; U/M: EA; Cap_F: 0.000001; Tolerance_%: 10; Value1: Unknown; VDC_V: 50; TaMin_C: -55; TaMax_C: 85
C53 C116 = C0603C104J4RACTU: CAP, CERM, 0.1uF, 16V, +/-5%, X7R, 0603; Manufacturer: Kemet; Polarized: N; CompType: Capacitor; U/M: EA; Cap_F: 0.0000001; Tolerance_%: 5; Value1: Unknown; VDC_V: 16; TaMin_C: -55; TaMax_C: 125
C54 C70 C74 = 06031C103JAT2A: 10000pF 100V Ceramic Capacitor X7R 0603; Manufacturer: AVX; Polarized: N; Value: 0.01uF; U/M: EA; Cap_F: 0.00000001; Tolerance_%: 5; ESR_ohm: 0.098; Value1: 0.098 ohm; VDC_V: 100; TaMin_C: -55; TaMax_C: 125; AEC Category: Q200
C57 C60 C67 C72 = GMK325AB7106MM-T: as C151 on sheet TIDA-00834_ISO-E2_Pg8_Split Rail Converter
C59 = UMK107ABJ474KA-T: CAP, CERM, 0.47uF, 50V, 10%, X5R, 0603; Manufacturer: Taiyo Yuden; Polarized: N; CompType: Capacitor; Cap_F: 0.00000047; Tolerance_%: 10; VDC_V: 50
C61 C62 = C0805C105K8RACTU: CAP, CERM, 1uF, 10V, +/-10%, X7R, 0805; Manufacturer: Kemet; Polarized: N; CompType: Capacitor; U/M: EA; Cap_F: 0.000001; Tolerance_%: 10; ESR_Ohm: 0.015; Value1: 0.015 ohm; IRMS_A: 8.19; TaMin_C: -55; TaMax_C: 125; Cap_Case: 0805
C63 C117 = C0603C104K8RACTU: CAP, CERM, 0.1uF, 10V, +/-10%, X7R, 0603; Manufacturer: Kemet; Polarized: N; CompType: Capacitor; U/M: EA; Cap_F: 0.0000001; Tolerance_%: 10; Value1: Unknown; TaMin_C: -55; TaMax_C: 125
C64 = EMK107BBJ106MA-T: CAP, CERM, 10uF, 16V, +/-20%, X5R, 0603; Manufacturer: Taiyo Yuden; Polarized: N; CompType: Capacitor; U/M: EA; Cap_F: 0.00001; Tolerance_%: 20; Value1: Unknown; VDC_V: 16; TaMin_C: -55; TaMax_C: 85
C65 = GRM31CR71E106KA12L: CAP, CERM, 10uF, 25V, +/-10%, X7R, 1206; Manufacturer: Wurth; Polarized: N; CompType: Capacitor; U/M: EA; Cap_F: 0.00001; Tolerance_%: 10; Value1: Unknown; VDC_V: 25; TaMin_C: -55; TaMax_C: 125; Cap_Case: 2220
C66 = 06033C104JAT2A: as C9 on sheet TIDA-00834_ISO-E2_Pg7_ COMPARATOR
C73 = C0805C225K8RACTU: as C153 on sheet TIDA-00834_ISO-E2_Pg8_Split Rail Converter
C166 = C1608X5R1V335K080AC: CAP, CERM, 3.3 µF, 35 V, +/- 10%, X5R, 0603; Manufacturer: TDK; Polarized: N; CompType: Capacitor; Value: 3.3uF; U/M: EA; Cap_F: 0.0000033; Tolerance_%: 10; ESR_ohm: 0.004796; Value1: 0.004796 ohm; VDC_V: 35; Value2: 35V; IRMS_A: 2.37519; TaMin_C: -55; TaMax_C: 85; SizeArea_mm2: 1.28; SizeAreaWB_mm2: 4.68; SizeX_mm: 1.6; SizeY_mm: 0.8; SizeZ_mm: 1; AEC Category: Q200
D8 = MMSZ4685-V: Diode, Zener, 3.6V, 500mW, SOD-123; Manufacturer: On semiconductor; U/M: EA; Power_W: 0.5; Vz_V: 3.6; Value1: 0.5W; RJA_CperW: 67
D10 D12 D14 D44 = LG L29K-G2J1-24-Z: LED, Green, SMD; Manufacturer: OSRAM; Vf_V: 1.7; Value2: 1.7V; Io_A: 0.002; Tjmax_C: 110; Value1: W; U/M: EA
D11 D13 = DZ2W15000L: as D5 on sheet TIDA-00834_ISO-E2_Pg8_Split Rail Converter
D43 = MMSZ5232B-7-F: Diode, Zener, 5.6 V, 500 mW, SOD-123; Manufacturer: Diodes Inc.; SymbolCreator: a0412235; U/M: EA; Power_W: 0.5; Vz_V: 5.6; Value1: 0.5W; RJA_CperW: 350; AEC Category: Q101
D45 = BAS316,115: Diode, Ultrafast, 100 V, 0.25 A, SOD-323; Manufacturer: NXP Semiconductor; U/M: EA; Vf_V: 1.4; Value: 100V; Value1: 0.25A; Value2: 1.4V; Io_A: 0.25; Vr_V: 100; TJmax_C: 150; AEC Category: Q101
FB1-FB3 = MMZ1608B102CTA00: Ferrite Bead, 1000 ohm @ 100 MHz, 0.3 A, 0603; Manufacturer: TDK; Imax_A: 0.3; DCR_ohm: 0.6; Value1: 0.6 ohm; Value2: 0.3A; ZTyp@100MHz_Ohm: 1000
J13 J47 = 5-146280-3: Header, 2.54mm, 3x1, Gold, TH; Manufacturer: TE Connectivity; SymbolCreator: a0799628; Pitch_mm: 2.54; Gender: Male; Shrouded: N; Row_Count: 1
R71 = CRCW0603300RJNEA: RES, 300 ohm, 5%, 0.1W, 0603; Manufacturer: Vishay-Dale; CompType: Resistor; Value_Code: 300R; Tolerance_%: 5; Power_W: 0.1; VDC_V: 75; TempCo: 200 ppm/C; EIA_Code: E24; U/M: EA
R72 R73 R77 R78 R81 R83 R189-R195 R242 R243 = CRCW06030000Z0EA: RES, 0 ohm, 5%, 0.1W, 0603; Manufacturer: Vishay-Dale; CompType: Resistor; Value_Code: 0000; Tolerance_%: 5; Power_W: 0.1; VDC_V: 75; TempCo: 200 ppm/C; EIA_Code: E24; U/M: EA
R74 R84 = CRCW06033K90JNEA: RES, 3.9k ohm, 5%, 0.1W, 0603; Manufacturer: Vishay-Dale; CompType: Resistor; Res_ohm: 3900; Value_Code: 3k90; Tolerance_%: 5; Power_W: 0.1; VDC_V: 75; TempCo: 200 ppm/C; EIA_Code: E24; U/M: EA
R75 R76 = CRCW12062K00FKEA: RES, 2.00 k, 1%, 0.25 W, 1206; Manufacturer: Vishay-Dale; CompType: Resistor; Value: 2.00k; Res_ohm: 2000; Value_Code: 2k00; Tolerance_%: 1; Power_W: 0.25; Value2: 0.25W; VDC_V: 200; TempCo: 100 ppm/C; SizeArea_mm2: 5.12; SizeX_mm: 3.2; SizeY_mm: 1.6; SizeZ_mm: 1.35; EIA_Code: E96; U/M: EA; AEC Category: Q200
R79 = CRCW06038K45FKEA: RES, 8.45 k, 1%, 0.1 W, 0603; Manufacturer: Vishay-Dale; CompType: Resistor; Value: 8.45k; Res_ohm: 8450; Value_Code: 8k45; Tolerance_%: 1; Power_W: 0.1; Value2: 0.1W; VDC_V: 75; TempCo: 100 ppm/C; SizeArea_mm2: 1.28; SizeX_mm: 1.6; SizeY_mm: 0.8; EIA_Code: E96; U/M: EA; AEC Category: Q200
R80 = CRCW0603100KFKEA: RES, 100 k, 1%, 0.1 W, 0603; Manufacturer: Vishay-Dale; CompType: Resistor; Value: 100k; Res_ohm: 100000; Tolerance_%: 1; Power_W: 0.1; Value2: 0.1W; VDC_V: 75; TempCo: 100 ppm/C; SizeArea_mm2: 1.28; SizeX_mm: 1.6; SizeY_mm: 0.8; EIA_Code: E96; U/M: EA; AEC Category: Q200
R82 = RNCF0603TKY10K0: as R27 on sheet TIDA-00834_ISO-E2_Pg7_ COMPARATOR
R85 = CRCW06031M07FKEA: RES, 1.07 M, 1%, 0.1 W, 0603; Manufacturer: Vishay-Dale; CompType: Resistor; Value: 1.07Meg; Res_ohm: 1070000; Value_Code: 1M07; Tolerance_%: 1; Power_W: 0.1; Value2: 0.1W; VDC_V: 75; TempCo: 100 ppm/C; SizeArea_mm2: 1.28; SizeX_mm: 1.6; SizeY_mm: 0.8; EIA_Code: E96; U/M: EA; AEC Category: Q200
R86 = RC0603FR-07100KL: as R24 on sheet TIDA-00834_ISO-E2_Pg7_ COMPARATOR
R87 = CRCW060331K6FKEA: RES, 31.6k ohm, 1%, 0.1W, 0603; Manufacturer: Vishay-Dale; CompType: Resistor; U/M: EA; Res_ohm: 31600; Value_Code: 31k6; Tolerance_%: 1; Power_W: 0.1; VDC_V: 75; TempCo: 100 ppm/C; EIA_Code: E96
R88 = CRCW060310K0FKEA: RES, 10.0k ohm, 1%, 0.1W, 0603; Manufacturer: Vishay-Dale; CompType: Resistor; U/M: EA; Res_ohm: 10000; Value_Code: 10k0; Tolerance_%: 1; Power_W: 0.1; VDC_V: 75; TempCo: 100 ppm/C; EIA_Code: E96
R241 = RC0603FR-07820RL: RES, 820, 1%, 0.1 W, 0603; Manufacturer: Yageo America; CompType: Resistor; Value: 820; Value_Code: 820R; Tolerance_%: 1; Power_W: 0.1; Value2: 0.1W; VDC_V: 150; TempCo: 200 ppm/C; SizeArea_mm2: 1.28; SizeX_mm: 1.6; SizeY_mm: 0.8; U/M: EA; AEC Category: Q200
SH-J10 SH-J38 = 881545-2: as SH-J3 on sheet TIDA-00834_ISO-E2_Pg7_ COMPARATOR
TP2 TP21 TP42 TP55 TP56 = 1573-2: as TP31 on sheet TIDA-00834_ISO-E2_Pg7_ COMPARATOR
TP19 TP20 TP22 = TP-040_RND: Test Point 40mil pad 20mil drill; Manufacturer: STD; Value: STD
TP23 = 5010: Test Point, Multipurpose, Red, TH; Manufacturer: Keystone; CompType: Test Point Loop; U/M: EA
TP24 = 5126: Test Point, Multipurpose, Green, TH; Manufacturer: Keystone; SymbolCreator: a0412235; CompType: Test Point Loop; U/M: EA
U7 = TPS7A6533QKVURQ1: IC, 300-mA 40-V LOW-DROPOUT REGULATOR WITH 25-uA QUIESCENT CURRENT; Manufacturer: TI; Alternate Manufacturer: None; Area: 136210
U8 = TLV1117-XXCDCY: IC,  vvV, 800mA LDO Voltage Regulators; Manufacturer: TI; Alternate Manufacturer: None; Area: 101500; Value: TLV1117I-xxCDCY
U9 U16 = OPA322AIDBVR: 20 MHz, Low Noise, RRIO, CMOS Operational Amplifier with Shutdown, 1.8 to 5.5 V, -40 to 125 degC, 5-pin SOT23 (DBV0005A), Green (RoHS & no Sb/Br); Manufacturer: Texas Instruments; Alternate Manufacturer: None; Alternate PartNumber: Equivalent; CMRR(Min)(dB): 90; GBW(Typ)(MHz): 20; IIB(Max)(pA): 10; Iq per channel(Max)(mA): 1.9; Number of Channels: 1; Offset Drift(Typ)(uV/C): 1.8; Packing: LARGE T&R; Rating: Catalog; Sub Family: High Output Current Amplifier (>=50mA), Low Input Bias Current Amp (<=10pA), Low Noise Amp (<=10nV/rtHz), Low Supply Voltage Amplifier (<=2.7V), Precision Amplifier; Total Supply Voltage(Max)(+5V is 5, +/-5V is 10): 5.5; Vio (25C)(Max)(mV): 2
U10 = REF5025AIDGKT: Low Noise, Very Low Drift, Precision Voltage Reference, -40 to 125 degC, 8-pin MSOP(DGK), Green (RoHS & no Sb/Br); Manufacturer: Texas Instruments; Alternate PartNumber: Equivalent; Initial Accuracy @ 25/deg C(%): 0.05; Iout/Iz(Max)(mA): 10; Iq(Max)(uA): 1000; Rating: Military; SubFamily: Series Voltage Reference; Temp Coeff(Max)(ppm/ degree C): 3; VI(Max)(V): 18; VI(Min)(V): 2.7; VO(V): 2.5
U11 = LP2951CSD: Series of Adjustable Micropower Voltage Regulators, 8-pin LLP; Manufacturer: Texas Instruments; PackageTopMarking: NS*UZXYTT*2951ACB; PowerWise: N; CompType: LDO IC
U12 = TPS7A3001DGNR: Single Output High PSRR LDO, 200 mA, Adjustable -1.18 to -33 V Output, -3 to -36 V Input, with Ultra-Low Noise, 8-pin MSOP (DGN), -40 to 125 degC, Green (RoHS & no Sb/Br); Manufacturer: Texas Instruments; Alternate PartNumber: Equivalent; Accuracy(%): 1.5; Iout(Max)(A): 0.2; Iq(Typ)(mA): 0.05; SubFamily: Single Channel LDO; Vdo(Typ)(mV): 216
U19 = REF3025AIDBZR: 2.5 V, 50 ppm / degC, 50 uA Series (Bandgap) Voltage Reference, -40 to 125 degC, 3-pin SOT-23 (DBZ), Green (RoHS & no Sb/Br); Manufacturer: Texas Instruments; Alternate PartNumber: Equivalent; Initial Accuracy @ 25/deg C(%): 0.2; Iq(Max)(uA): 50; Rating: Catalog; SubFamily: Series Voltage Reference; Temp Coeff(Typ)(ppm/ degree C): 20; VI(Max)(V): 5.5; VI(Min)(V): 2.501; VO(V): 2.5

## Sheet TIDA-00834_ISO-E2_Pg10_ ISOPOWER.SchDoc: ISOLATED POWER
size 431 x 279 mm; Date: Not shown in title block; ApprovedBy: Not shown in title block; CheckedBy: Not shown in title block; Author: Not shown in title block; CompanyName: Not shown in title block; DrawnBy: Sreenivasa; Engineer: Not shown in title block; Organization: Not shown in title block; Address1: Not shown in title block; Address2: Not shown in title block; Address3: Not shown in title block; Address4: Not shown in title block; DocumentNumber: 1; Revision: Use project parameter SCH_Rev; SheetNumber: 10; SheetTotal: 12; PageSetup: Record=PageOptions¦CenterHorizontal=True¦CenterVertical=True¦PrintScale=1.00¦XCorrection=1.00¦YCorrection=1.00¦PrintKind=0¦BorderSize=5000000¦LeftOffset=0¦BottomOffset=0¦Orientation=2¦PaperLength=1000¦PaperWidth=1000¦Scale=100¦PaperSource=15¦PrintQuality=600¦MediaType=1¦DitherType=10¦PaperKind=Letter¦PrintScaleMode=1
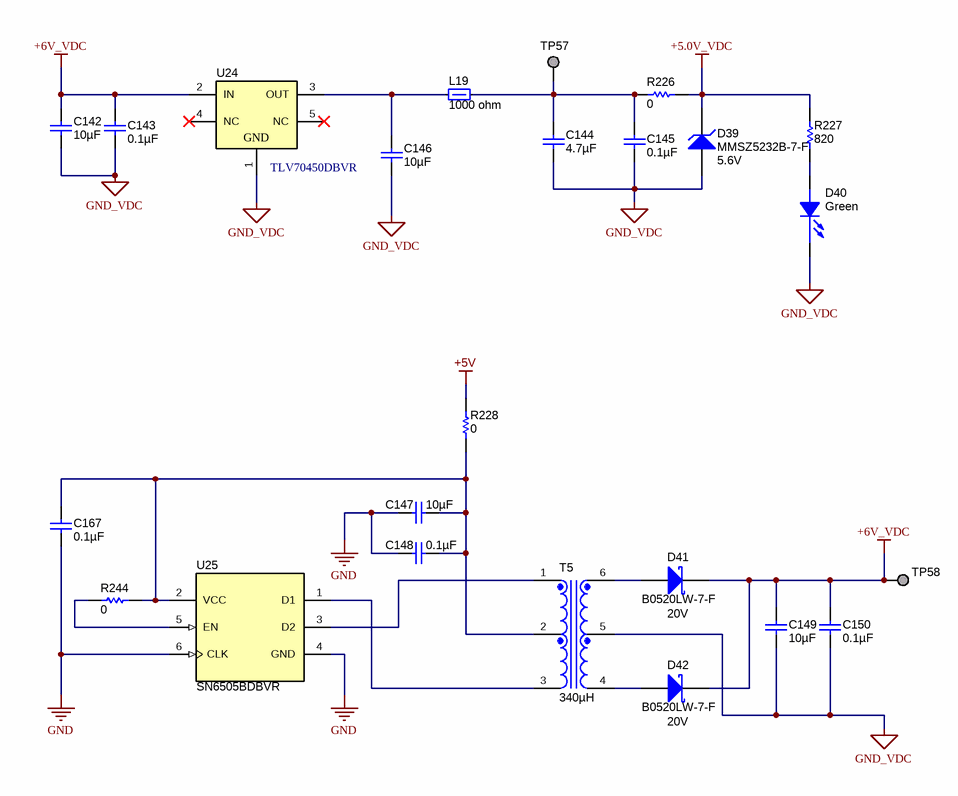
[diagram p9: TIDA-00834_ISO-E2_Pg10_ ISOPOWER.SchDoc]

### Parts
C142  ValueDisplayed: 10µF  [1210]
C143  ValueDisplayed: 0.1µF  [0603]
C144  ValueDisplayed: 4.7µF  [0805_HV]
C145  ValueDisplayed: 0.1µF  [0603]
C146  ValueDisplayed: 10µF  [1210]
C147  ValueDisplayed: 10µF  [1210]
C148  ValueDisplayed: 0.1µF  [0603]
C149  ValueDisplayed: 10µF  [1210]
C150  ValueDisplayed: 0.1µF  [0603]
C167  ValueDisplayed: 0.1µF  [0603]
D39  MMSZ5232B-7-F  value 5.6V  [SOD-123]
D40  value Green  [LED0603AA]
D41  B0520LW-7-F  value 20V  [SOD-123]
D42  B0520LW-7-F  value 20V  [SOD-123]
L19  value 1000 ohm  [MMZ1608_095]  (hidden comment: MMZ1608B102CTA00)
R226  value 0  [0603]  (hidden comment: CRCW06030000Z0EA)
R227  ValueDisplayed: 820  [0603]  (hidden comment: RC0603FR-07820RL)
R228  value 0  [0603]  (hidden comment: CRCW06030000Z0EA)
R244  value 0  [0603]  (hidden comment: CRCW06030000Z0EA)
T5  ValueDisplayed: 340µH  [Wurth_750313638]  (hidden comment: 750313638)
TP57  Pogo Pad  [PogoPad]  (value not drawn)  (no BOM)
TP58  Pogo Pad  [PogoPad]  (value not drawn)  (no BOM)
U24  TLV70450DBVR  [DBV0005A_N]
U25  SN6505BDBVR  [DBV0006A_N]

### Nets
+5.0V_VDC: D39.1(K) R226.2 R227.2
+5V: R228.2
+6V_VDC: C142.2 C143.1 C149.1 C150.1 D41.1(K) D42.1(K) TP58.1 U24.2(IN)
GND: C147.1 C148.1 C167.1 U25.4(GND) U25.6(CLK)
GND_VDC: C142.1 C143.2 C144.1 C145.2 C146.1 C149.2 C150.2 D39.2(A) D40.1(C) T5.5 U24.1(GND)
NetC144_2: C144.2 C145.1 L19.2 R226.1 TP57.1
NetC146_2: C146.2 L19.1 U24.3(OUT)
NetC147_2: C147.2 C148.2 C167.2 R228.1 R244.1 T5.2 U25.2(VCC)
NetD40_2: D40.2(A) R227.1
NetD41_2: D41.2(A) T5.6
NetD42_2: D42.2(A) T5.4
NetR244_2: R244.2 U25.5(EN)
NetT5_1: T5.1 U25.3(D2)
NetT5_3: T5.3 U25.1(D1)

Not connected (* = marked no-connect by the designer): U24 4(NC)* 5(NC)*

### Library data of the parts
C142 C146 C147 C149 = GMK325AB7106MM-T: as C151 on sheet TIDA-00834_ISO-E2_Pg8_Split Rail Converter
C143 C145 C148 C150 C167 = C0603C104K5RACTU: as C46 on sheet TIDA-00834_ISO-E2_Pg9_LDO
C144 = C2012X5R1H475K125AB: 4.7µF ±10% 50V X5R Ceramic Capacitor -55°C ~ 85°C; PartNumber: GRM21BR61H475KE51L; Manufacturer: TDK; Polarized: N; Value: 4.7uF; U/M: EA; Cap_F: 0.0000047; Tolerance_%: 10; Value1: Unknown; VDC_V: 50; TaMin_C: -55; TaMax_C: 85; Cap_Case: 0805
D39 = MMSZ5232B-7-F: as D43 on sheet TIDA-00834_ISO-E2_Pg9_LDO
D40 = LED_LG L29K-G2J1-24-Z: LED SmartLED Green 570NM; Manufacturer: OSRAM; SymbolCreator: x0120606
D41 D42 = MBR0520LT1G: Diode, Schottky, 20V, 0.5A, SOD-123; Manufacturer: Diodes Inc; U/M: EA; Vf_V: 0.385; Value2: 0.385V; Io_A: 0.5; Vr_V: 20; TJmax_C: 125; RJC_CperW: 150
L19 = MMZ1608B102CTA00: as FB1 on sheet TIDA-00834_ISO-E2_Pg9_LDO
R226 R228 R244 = CRCW06030000Z0EA: as R72 on sheet TIDA-00834_ISO-E2_Pg9_LDO
R227 = RC0603FR-07820RL: as R241 on sheet TIDA-00834_ISO-E2_Pg9_LDO
T5 = 750313734: Transformer, 340 uH, TH; Manufacturer: Wurth Elektronik; SymbolCreator: Altium; Value: 340uH; Lp: 340; DCR_ohm: 0.419
TP57 TP58 = PogoPad: as TP1 on sheet TIDA-00834_ISO-E2_Pg8_Split Rail Converter
U24 = TLV70450DBVR: Single Output LDO, 150 mA, Fixed 5 V Output, 2.5 to 24 V Input, with Ultra-Low IQ, 5-pin SOT-23 (DBV), -40 to 125 degC, Green (RoHS & no Sb/Br); Manufacturer: Texas Instruments; Alternate PartNumber: Equivalent; Accuracy(%): 2; Fixed Output Options(V): 5; Iout(Max)(A): 0.15; Iq(Typ)(mA): 0.003; SubFamily: Single Channel LDO; Vdo(Typ)(mV): 400; Vin(Max)(V): 24; Vin(Min)(V): 2.5
U25 = SN6505BDBVR: LOW-NOISE 1A TRANSFORMER DRIVERS FOR ISOLATED POWER SUPPLIES, DBV0006A; Alternate PartNumber: SN6505BDBVT; Manufacturer: Texas Instruments; SymbolCreator: Altium; CompType: IC; U/M: EA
